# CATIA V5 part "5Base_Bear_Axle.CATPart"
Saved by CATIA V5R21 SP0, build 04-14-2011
Part number: Base_Bear_Axle
Bounding box of the stored display mesh (mm): x -15 to 15, y -15 to 15, z 0 to 11
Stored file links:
  F:\教程\Robotic_Arm_Arduino_Kinect\机械臂CAD\Arm_Detailed_Design\Base_Bear_Axle.CATPart
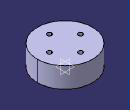
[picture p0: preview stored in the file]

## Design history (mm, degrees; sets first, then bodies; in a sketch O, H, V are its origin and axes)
Body1 (main body)
  Sketch1 on xy-plane, origin (0, 0, 0), H (1, 0, 0), V (0, 1, 0)
    circle A1 centre (0, 0) radius 15
    radius A1 = 15
  Pad1: profile Sketch1, direction (0, 0, 1), length 11
  Sketch2 on start face of Pad1, origin (0, 0, 0), H (1, 0, 0), V (0, -1, 0)
    circle A1 centre (0, 0) radius 12
    reference projected circle E1 centre (0, 0) radius 15 from edge [start face of Pad1 | face of Pad1 from Sketch1.A1]
    distance A1 E1 = 3
  Pocket1: profile Sketch2, direction (0, 0, 1), up to end face of Pad1, offset -3
  Sketch3 on end face of Pad1, origin (0, 0, 11), H (1, 0, 0), V (0, 1, 0)
    circle A1 centre (0, 8.5) radius 1.25
    point P1 (0, 8.5)
    circle A2 centre (8.5, 0) radius 1.25
    point P2 (8.5, 0)
    circle A3 centre (0, -8.5) radius 1.25
    point P3 (0, -8.5)
    circle A4 centre (-8.5, 0) radius 1.25
    point P4 (-8.5, 0)
    point P5 (-7.25, 0)
    radius A1 = 1.25
    radius A2 = 1.25
    radius A3 = 1.25
    radius A4 = 1.25
    distance P1 H = 8.5
    distance P2 V = 8.5
    distance P3 H = 8.5
    distance V P4 = 8.5
    coincidence: P1 V, P2 H, P3 V, P4 H, A4 P5, P5 H
  Pocket2: profile Sketch3, direction (0, 0, -1), through (limit type 3)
